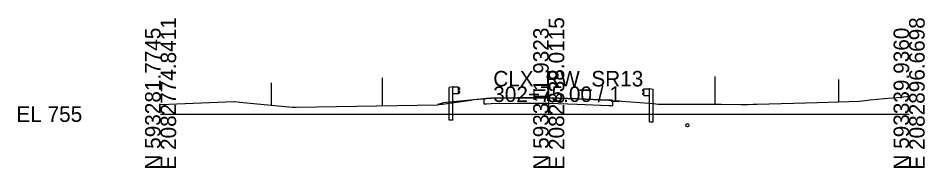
# Model space of a CAD drawing. Extents: x -26 to 2138, y -10 to 4518.
# Drawn here: x -25.7 to 137.8, y 2990.3 to 3017.3 of the extents above; entities that cross this region are included whole.
import ezdxf

# ---------------------------------------------------------------- set-up
doc = ezdxf.new("R2010")
doc.units = 0
for name, color, linetype in [('GK_Cells', 7, 'Continuous'), ('MD_X_Asphalt_Pavement', 7, 'Continuous'), ('RD_P_Cells', 7, 'Continuous'), ('RW_P_Esmt_SH', 7, 'Continuous'), ('RW_X_Esmt_SH', 7, 'Continuous'), ('UT_X_Water', 7, 'Continuous'), ('XS_P_Finished_Grade', 7, 'Continuous'), ('XS_X_Ground_Line', 7, 'Continuous')]:
    doc.layers.add(name, color=color, linetype=linetype)

msp = doc.modelspace()

# ---------------------------------------------------------------- linework, layer by layer
at = {"layer": 'GK_Cells'}
for p, q in [((70, 3000), (70, 3005)), ((0, 3000), (70, 3000)), ((70, 3000), (135, 3000))]:
    msp.add_line(p, q, dxfattribs=at)
at = {"layer": 'MD_X_Asphalt_Pavement'}
msp.add_lwpolyline([(64.34, 3002.92), (59.61, 3002.86), (58.77, 3002.82), (58.3, 3002.79), (58.3, 3001.84), (58.77, 3001.86), (59.61, 3001.9), (64.34, 3001.96), (70.01, 3002.01), (75.14, 3001.79), (80.82, 3001.59), (81.3, 3001.56), (81.56, 3001.53), (81.56, 3002.49), (81.3, 3002.52), (80.82, 3002.55), (75.14, 3002.75), (70.01, 3002.97), (64.34, 3002.92)], dxfattribs=at)
at = {"layer": 'RD_P_Cells'}
for p, q in [((52.1, 3004.82), (52.05, 3004.8)), ((52.05, 2998.91), (52.05, 3004.8)), ((52.64, 3004.91), (52.1, 3004.82)), ((52.72, 3004.87), (52.64, 3004.91)), ((53.72, 3004.87), (52.72, 3004.87)), ((52.72, 2998.91), (52.72, 3004.87)), ((53.72, 3003.68), (53.72, 3004.87)), ((53.81, 3004.77), (53.72, 3004.78)), ((53.73, 3004.27), (53.73, 3004.32)), ((53.73, 3004.22), (53.73, 3004.27)), ((53.76, 3004.38), (53.97, 3004.52)), ((53.97, 3004.02), (53.76, 3004.16)), ((53.97, 3004.65), (53.81, 3004.77)), ((86.93, 3004.36), (87.09, 3004.47)), ((87.14, 3004.09), (86.93, 3004.23)), ((87.09, 3004.47), (87.18, 3004.49)), ((87.18, 3003.38), (87.18, 3004.57)), ((87.18, 3004.57), (88.18, 3004.57)), ((88.18, 3004.57), (88.26, 3004.61)), ((88.18, 2998.61), (88.18, 3004.57)), ((88.26, 3004.61), (88.8, 3004.53)), ((88.8, 3004.53), (88.85, 3004.51)), ((88.85, 2998.61), (88.85, 3004.51)), ((53.72, 3003.68), (52.72, 3003.68)), ((53.72, 3003.76), (53.81, 3003.78)), ((53.81, 3003.78), (53.97, 3003.89)), ((86.93, 3003.72), (87.14, 3003.86)), ((87.09, 3003.48), (86.93, 3003.59)), ((87.18, 3003.46), (87.09, 3003.48)), ((87.17, 3003.98), (87.17, 3004.02)), ((87.17, 3003.93), (87.17, 3003.98)), ((87.18, 3003.38), (88.18, 3003.38)), ((52.72, 2998.91), (52.05, 2998.91)), ((88.18, 2998.61), (88.85, 2998.61))]:
    msp.add_line(p, q, dxfattribs=at)
for points in [[(53.74, 3004.33), (53.74, 3004.21), (53.73, 3004.21), (53.73, 3004.33)], [(53.74, 3004.3), (53.74, 3004.24), (53.76, 3004.24), (53.76, 3004.3)], [(87.16, 3004), (87.16, 3003.95), (87.14, 3003.95), (87.14, 3004)], [(87.16, 3004.04), (87.16, 3003.92), (87.17, 3003.92), (87.17, 3004.04)]]:
    msp.add_lwpolyline(points, close=True, dxfattribs=at)
for centre, start, end in [((53.81, 3004.32), 124.962, 180), ((53.81, 3004.22), 180, 235.038), ((53.92, 3004.59), 304.962, 54.7677), ((86.98, 3004.29), 125.2323, 235.038), ((53.92, 3003.95), 304.962, 54.7677), ((86.98, 3003.66), 125.2323, 235.038), ((87.09, 3004.02), 0, 55.038), ((87.09, 3003.93), 304.962, 0)]:
    msp.add_arc(centre, 0.0781, start, end, dxfattribs=at)
at = {"layer": 'RW_P_Esmt_SH'}
for p, q in [((122.35, 3002.24), (122.35, 3006.24)), ((20, 3001.63), (20, 3005.63))]:
    msp.add_line(p, q, dxfattribs=at)
at = {"layer": 'RW_X_Esmt_SH'}
for p, q in [((40, 3001.54), (40, 3006.54)), ((100, 3001.79), (100, 3006.79))]:
    msp.add_line(p, q, dxfattribs=at)
at = {"layer": 'UT_X_Water'}
msp.add_circle((95, 2998.01), 0.3, dxfattribs=at)
at = {"layer": 'XS_P_Finished_Grade'}
for p, q in [((58.3, 3002.79), (51.05, 3002.07)), ((51.05, 3002.07), (49.99, 3001.72))]:
    msp.add_line(p, q, dxfattribs=at)
at = {"layer": 'XS_X_Ground_Line'}
msp.add_lwpolyline([(0, 3001.77), (13.29, 3002.27), (13.33, 3002.26), (13.33, 3002.26), (13.34, 3002.25), (13.39, 3002.26), (14.31, 3002.18), (23.72, 3001.26), (24.17, 3001.27), (24.46, 3001.27), (49.92, 3001.71), (50.58, 3001.79), (50.87, 3001.83), (55.93, 3002.54), (56.56, 3002.63), (58.3, 3002.79), (58.77, 3002.82), (59.61, 3002.86), (64.34, 3002.92), (70.01, 3002.97), (75.14, 3002.75), (80.82, 3002.55), (81.3, 3002.52), (81.56, 3002.49), (88.04, 3001.98), (88.89, 3001.91), (89.72, 3001.83), (101.09, 3001.78), (104.71, 3001.74), (105.07, 3001.74), (105.24, 3001.75), (105.28, 3001.75), (105.38, 3001.75), (106, 3001.77), (106.88, 3001.79), (107.57, 3001.81), (118.49, 3002.13), (126.04, 3002.34), (127.98, 3002.56), (130.52, 3002.85), (133.49, 3003.06), (135, 3003.22)], dxfattribs=at)

# ---------------------------------------------------------------- texts
msp.add_text('-', height=0.0001).set_placement((0, 3000))
at = {"layer": 'GK_Cells'}
for s, p in [('E 2082774.8411', (2.8, 2990)), ('E 2082838.0115', (72.8, 2990)), ('E 2082896.6698', (137.8, 2990)), ('N 593281.7745', (0, 2990)), ('N 593311.9323', (70, 2990)), ('N 593339.9360', (135, 2990))]:
    msp.add_text(s, height=2.8, rotation=90, dxfattribs=at).set_placement(p)
for s, p in [('CLX_RW_SR13', (60, 3005)), ('302+75.00 / 1', (60, 3002.2)), ('EL 755', (-26, 2998.6))]:
    msp.add_text(s, height=2.8, dxfattribs=at).set_placement(p)

doc.saveas('drawing.dxf')
